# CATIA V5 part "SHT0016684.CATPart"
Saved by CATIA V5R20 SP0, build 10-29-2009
Part number: SHT0016684
Source: Unknown
Bounding box of the stored display mesh (mm): x 1034.67 to 1473.999, y -488.979 to -424.979, z 40 to 152.7
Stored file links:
  E:\李燕龙\吉利商用车G3\07 设计变更\ECR0009849--标配底支架后移50mm设计变更\数据图纸\SHT0015279-标配底支架左边板\SHT0016684.CATPart
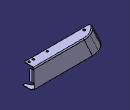
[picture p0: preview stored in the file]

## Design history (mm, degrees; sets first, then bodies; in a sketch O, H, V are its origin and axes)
Body1 "几何体.76" (main body)
  Solid1: solid without history
  RemoveFace1: RemoveFaces (face of Solid1; face of Solid1; face of Solid1; face of Solid1)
